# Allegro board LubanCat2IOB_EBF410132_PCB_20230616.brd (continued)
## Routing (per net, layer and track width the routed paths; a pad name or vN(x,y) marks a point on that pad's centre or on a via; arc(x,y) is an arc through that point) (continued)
VCC3V3_SD: length 133.2
  TOP w0.254: J1.15 35.78,21.16 36.04,20.9 36.28,21.14 J1.17
  TOP w0.381: v1(135.98,23.52) 133.25,23.52 132.66,22.93 v1(132.66,11.91) ; v1(37.05,11.26) 35.96,11.26 35.36,11.86 35.36,19.78 36.04,20.47 36.04,20.9
  ART03 w0.381: v1(37.05,11.26) 37.06,11.25 127.48,11.25 128.14,11.91 v1(132.66,11.91)
  BOTTOM w0.381: v1(135.98,23.52) C28.1 136.66,23.65 137.21,24.2 139.6,24.2 140.2,23.6 C30.1 J41.4
VCC5V0_SYS: length 183.1
  TOP w0.305: v1(135.52,97.61) 132.56,97.61 131.55,96.59 105.77,96.59 105.26,96.08 105.26,95.14 104.65,94.53 99.54,94.53 98.98,95.09 98.98,97.81 98.22,98.57 32.05,98.57 30.28,96.8 26.64,96.8 25.35,98.09 21.23,98.09 18.97,95.83 15.82,95.83 14.71,94.71 14.71,80.29 16.1,78.89 16.1,74.09 15.39,73.38 12.93,73.38 12.22,72.67 12.22,61.08 ; 10.19,60.91 10.19,71.11 9.88,71.41 C24.2 R11.2
  BOTTOM w0.305: R4.1 v1(135.52,97.61)
VCC5V0_USB: length 12.3
  TOP w0.305: R235.2 C140.2 5.44,72.72 v1(7.57,72.72)
  BOTTOM w0.305: C141.1 13.55,77.01 v1(14.04,77.49) ; v1(7.57,72.72) 11.02,72.72 11.55,73.24 C159.1
  vias: v1(14.04,76.49) v1(15.04,77.49) v1(15.04,76.49) v1(31.11,86.66) v1(31.11,85.66) v1(32.11,86.66) v1(32.11,85.66) v1(117.02,82.54) v1(118.02,82.54) v1(119.02,82.54) v1(121.59,97.48) v1(122.59,98.48) v1(122.59,97.48) v1(128.82,97.48) v1(129.82,98.48) v1(129.82,97.48)
VCC5V0_USB20_HOST2: length 16.3
  BOTTOM w0.508: C144.1 126,96.46 ; 126,96.46 126.62,97.08 126.62,98.03 126.11,98.54 C145.1 125.81,98.44 U24.1 ; 126,96.46 126.11,96.46 126.62,95.95 126.62,92.33 127.05,91.89 128.19,91.89 128.7,91.39 128.7,90.14 129.31,89.53 129.31,87.71 J19.10
VCC5V0_USB20_HUB: length 45.8
  TOP w0.305: J20.7 111.1,93.06 110.49,93.67 99.01,93.67 98.11,94.57 v1(97.21,94.57)
  TOP w0.508: U29.1 112.87,81.31 C161.1 C162.1 C165.1 C164.1 109.75,84.15 J20.1 J20.7
  BOTTOM w0.305: U28.19 105.37,97.24 104.06,98.56 C154.1 104,98.59 103.43,99.16 102.05,99.16 101.46,98.58 C155.1 101.46,97.81 101.13,97.48 97.64,97.48 97.21,97.05 v1(97.21,94.57)
VCC5V0_USB30_HOST: length 14.3
  BOTTOM w0.508: J19.1 129.85,93.24 131.34,94.74 134.16,94.74 134.52,95.09 134.52,97.41 133.93,97.99 C148.1 C149.1 132.26,98.44 U26.1
VCC_1V8: length 245.6
  TOP w0.254: J1.13 35.28,21.28 35.03,21.03 34.78,21.27 J1.11
  TOP w0.305: v1(17.36,34.58) 20.38,34.58 v1(20.43,34.63) 20.43,19.6 21.04,19 34.04,19
  TOP w0.381: v1(62.18,67.75) 62.2,67.74 L10.2 ; v1(63.75,16.68) C23.1 C22.1 v1(61.97,18.83) 61.97,16.6 61.52,16.15 61.52,8 60.78,7.26 35.33,7.26 34.75,7.84 34.75,18.28 34.04,19 34.65,19.6 34.65,20.14 35.03,20.52 35.03,21.03 ; L14.2 v1(81.43,67.74)
  ART04 w0.381: v1(61.97,18.83) 62.21,19.07 78.26,19.07 78.74,19.55 78.74,24.99 77.14,26.59 77.14,58.67 79.22,60.75 79.22,63.14 81.43,65.34 v1(81.43,67.74)
  BOTTOM w0.381: Q1.1 16.9,33.35 R45.1 v1(17.36,34.58) ; v1(62.18,67.75) 56,67.75 53.64,65.4 53.64,62.28 55.42,60.5 55.42,43.25 56.16,42.52 65.38,42.52 66.14,41.75 66.14,26.03 65.74,25.62 59.44,25.62 59.01,25.2 59.01,23.41 59.28,23.14 60.86,23.14 61.07,22.92 61.08,22.92 ; 61.08,22.92 R24.1 61.08,19.71 v1(61.97,18.83) ; 61.08,22.92 61.32,23.16 62.91,23.16 63.24,22.83 R25.1 ; U6.8 v1(63.75,16.68) ; v1(20.43,34.63) R46.1 19.98,33.4 Q2.1
VCCA_1V8: length 45
  TOP w0.254: J1.14 35.28,27.64 v1(35.04,27.89) 34.78,27.64 J1.12
  TOP w0.305: v1(64.28,30.89) 64.83,30.34 R219.1
  BOTTOM w0.381: v1(35.04,27.89) 35.68,27.25 52.04,27.25 52.5,26.79 54.79,26.79 55.32,27.33 55.32,29.21 54.94,29.59 53.98,29.59 53.41,30.16 53.41,32.57 53.98,33.14 63.5,33.14 64.28,32.36 v1(64.28,30.89)
VCCIO_ACODEC: length 73.1
  TOP w0.254: J1.19 36.78,23.64 v1(37.04,23.89) 37.28,23.64 J1.21
  TOP w0.381: v1(38.74,77.85) 38.74,76.53 38.36,76.15 v1(32.97,76.15)
  ART04 w0.381: v1(37.04,23.89) 37.04,46.63 36.27,47.39 34.04,47.39 33.27,48.15 33.27,62.51 31.65,64.13 31.65,74.82 v1(32.97,76.15)
  BOTTOM w0.381: R210.1 v1(38.74,77.85) R213.1
VDD_3V3: length 89.3
  TOP w0.305: R147.1 R146.1 61.32,70.44 v1(62.17,71.29) ; R6.2 C14.2 9.74,43.47 10.13,43.07 10.13,33.4 10.16,33.37 ; U12.5 3.07,23.16 3.29,22.94 4.31,22.94 4.57,23.2 v1(4.57,23.79) C21.1 ; U35.5 v1(144.08,64.88) ; C17.1 v1(8.76,23.79) 8.76,23.45 8.48,23.16 7.48,23.16 7.26,23.38 U4.5 ; U40.5 143.15,42.19 143.43,41.91 v1(144.71,41.91) ; L16.2 v1(82.21,80.43) ; L12.2 v1(63.11,80.25) ; v1(60.32,18.83) R33.1 R35.1
  TOP w0.381: L15.2 81.58,70.4 v1(81.31,70.13) ; v1(37.06,17.68) 36.54,18.2 L6.1 ; L7.2 66.38,16.6 65.81,16.02 63.41,16.02 v1(62.75,16.68) ; L11.2 63.06,70.4 v1(62.17,71.29) ; v1(47.57,17.68) 47.08,18.18 L5.1
  PWR05 w0.508: 12,14.97 J37.5 ; J37.5 12.73,15.7 ; J37.5 11.27,15.7 ; J37.5 12,16.43
  BOTTOM w0.305: R178.1 55.97,71.19 Q6.1 ; v1(9.76,85.21) 10.14,84.84 R72.1 ; R66.2 v1(150.5,95.86) ; v1(19.08,84.25) v1(19.08,83.25) 19.82,82.51 D21.2 ; v1(7.55,78.8) 7.55,77.7 7.23,77.38 R236.2 ; R180.1 52.88,70.74 53.19,71.04 53.19,72.31 53.49,72.61 55.14,72.61 Q6.1 ; v1(1.53,52.51) 4.21,52.51 4.44,52.74 R2.2 ; Q8.1 59.27,71.19 R181.1 ; Q8.1 58.5,72.56 56.74,72.56 Q6.1 ; Q8.1 59.84,72.36 61.87,72.36 62.17,72.06 v1(62.17,71.29) ; R48.1 v1(22.12,28.72) ; R31.1 v1(140.22,97.35) ; R47.1 v1(16.66,28.72) ; R32.1 v1(146.81,95.83)
  BOTTOM w0.381: U9.5 32.04,20.6 C37.1 v1(33.22,20.25) ; v1(20.82,18.09) 21.34,18.62 C40.1 21.34,19.11 U10.5
  vias: v1(9.17,32.46) v1(9.17,31.46) v1(10.17,32.46) v1(10.17,31.46) v1(11.17,32.46) v1(11.17,31.46) v1(96.42,22.94) v1(96.42,22.14) v1(142.66,13.29) v1(142.66,12.29) v1(143.08,65.88) v1(143.66,13.29) v1(143.66,12.29) v1(144.08,65.88) v1(145.71,41.91)
VDD_3V3_EDP_LCD: length 32.5
  TOP w0.305: J29.12 152.81,22.05 153.03,22.27 152.76,22.55 J29.13 ; R187.1 v1(149.22,20.75)
  TOP w0.508: 153.03,22.27 v1(153.39,22.27) 155.57,22.27 156.08,21.76 156.08,13.69 155.45,13.05 149.1,13.05 148.59,13.56 C184.1 C183.1 147.5,14.21 U37.1
  BOTTOM w0.305: v1(149.22,20.75) 153.09,20.75 153.39,21.05 v1(153.39,22.27)
VDD_3V3_EDP_TP: length 17.4
  BOTTOM w0.508: v1(104.16,20.62) v1(105.16,20.62) 105.92,20.62 108.1,22.81 112.17,22.81 112.73,22.25 112.73,14.84 J28.1
VDD_5V: length 65.8
  TOP w0.305: v1(144.08,68.72) 143.98,68.82 U36.5 ; U33.5 v1(144.08,57.52) ; C4.1 9.4,46.78 v1(9.17,46.55) ; 10.19,47.24 10.16,47.27 10.16,56.92 9.63,57.44 C2.2 R1.2 ; U39.5 143.15,37.8 v1(143.71,37.24) v1(144.71,37.24) v1(144.71,38.24) ; U34.5 v1(144.08,60.82)
  TOP w0.508: J37.3 16,16.43 ; J37.3 16,14.97 ; J37.3 16.73,15.7 ; J37.3 15.27,15.7
  ART04 w0.305: v1(47.26,90.8) v1(48.26,90.8)
  BOTTOM w0.305: Q7.1 51.46,72.74 49.43,72.74 48.95,73.22 48.95,90.7
  BOTTOM w0.381: 19.68,24.17 20.07,24.56 U10.3 ; 19.68,24.17 20.12,23.73 20.12,22.98 20.5,22.6 23.09,22.6 23.5,22.2 C38.1 23.99,19.09 24.23,19.33 U9.3 ; 19.68,24.17 C41.1 16.13,24.66 v1(15.9,24.89)
  vias: v1(9.17,45.55) v1(10.17,46.55) v1(10.17,45.55) v1(11.17,46.55) v1(11.17,45.55) v1(28.32,80.67) v1(29.32,80.67) v1(133.2,59.59) v1(133.2,58.59) v1(134.2,59.59) v1(134.2,58.59) v1(135.18,59.59) v1(135.2,58.59) v1(143.08,69.72) v1(143.08,61.72) v1(143.08,58.59) v1(144.08,69.72) v1(144.08,61.72) v1(144.08,58.59)
VDD_CAM0_5V: length 10.9
  TOP w0.305: C171.1 149.23,57.59 v1(149.28,57.54) v1(150.28,57.54)
  TOP w0.508: C171.1 C170.1 147.5,57.52 U33.1
  BOTTOM w0.305: J22.3 149.36,52.28 ; J22.1 149.36,51.28 ; J22.2 149.36,51.78
VDD_CAM1_5V: length 3
  TOP w0.508: U36.1 147.38,68.82 C174.1 C175.1
  vias: v1(149.28,69.01) v1(150.28,69.01)
VDD_LCD0_3V3: length 12.2
  TOP w0.305: J23.4 150.61,65.93 150.34,66.19 150.58,66.43 J23.5
  TOP w0.508: 150.34,66.19 149.71,66.19 149.49,65.97 v1(149.27,65.97) C190.1 C185.1 147.58,65.96 C191.1 147.52,64.88 U35.1
  BOTTOM w0.305: v1(149.27,65.97) 147.76,65.97 147.46,66.27 R222.1 R167.1
VDD_LCD0_5V: length 8.5
  TOP w0.508: 151.51,63.8 151.51,62.51 150.9,61.9 C186.1 C188.1 147.58,61.9 C187.1 147.52,60.82 U34.1
VDD_LCD1_3V3: length 10.8
  TOP w0.305: R224.1 v1(146.71,47.24) ; U40.1 147.52,43.04 C198.1 147.57,43.11 C196.1 C199.1 ; R223.1 v1(146.71,46.15)
  BOTTOM w0.305: v1(146.71,47.24) v1(146.71,46.15) 147.37,45.49 147.37,44.52 147.68,44.22 v1(149.35,44.22)
VDD_LCD1_5V: length 6.5
  TOP w0.508: 151.08,40.06 C194.1 C197.1 147.58,40.05 C195.1 147.52,38.97 U39.1
BAT_RTC: length 11
  BOTTOM w0.305: J16.1 17.92,77.47 18.22,77.77 22.38,77.77 22.64,78.03 D24.2 21.96,80.71 C67.1 22.42,81.81 D21.1
CAM0_NRST: length 125.8
  TOP w0.203: J2.76 75.78,27.89 75.78,30.34 76.1,30.65 121.41,30.65 123.6,28.47 132.74,28.47 v1(133.4,29.13)
  ART03 w0.142: v1(146.69,60.12) 146.69,57.68 146.35,57.35 144.77,57.35 v1(144.08,56.66)
  BOTTOM w0.203: v1(133.4,29.13) 133.4,31.41 133.71,31.72 150.82,31.72 151.26,32.16 151.26,48.23 150.85,48.64 144.45,48.64 144.08,49 v1(144.08,56.66) ; J22.22 147.59,61.78 146.69,60.88 v1(146.69,60.12)
CAM0_PWDN: length 183.8
  TOP w0.156: v1(43.05,10.26) 43.99,11.2 43.99,18.82 41.78,21.03 J1.39
  ART03 w0.142: v1(129.18,10.5) 129.18,9.96 128.89,9.67 101.27,9.67 99.35,7.75 82.41,7.75 80.87,9.29 44.02,9.29 v1(43.05,10.26)
  BOTTOM w0.156: J22.15 149.17,58.28 148.82,57.93 145.64,57.93 145.29,57.58 145.29,50.52 145.69,50.11 151.6,50.11 151.94,49.77 151.94,23.4 151.6,23.06 148.85,23.06 148.44,22.64 148.44,13.1 148.12,12.79 129.5,12.79 129.18,12.47 v1(129.18,10.5)
CAM0_PWR_EN: length 118.7
  TOP w0.156: v1(122.42,48.74) 121.89,49.27 111.15,49.27 110.83,49.59 110.83,54.47 110.52,54.78 97.23,54.78 94.51,52.07 46.1,52.07 45.78,52.38 J3.56 ; R174.1 v1(140.6,58.59)
  BOTTOM w0.156: v1(122.42,48.74) 122.51,48.74 123.22,49.45 123.22,52.64 123.53,52.96 140.44,52.96 140.6,53.11 v1(140.6,58.59)
CAM1_NRST: length 141.2
  TOP w0.203: J2.80 76.78,27.89 76.78,29.53 77.1,29.84 121,29.84 123.24,27.61 133.88,27.61 v1(135.4,29.13)
  ART04 w0.203: v1(153,79.61) 153,80.27 153.19,80.46 156.13,80.46 156.54,80.06 156.54,30.84 156.26,30.55 135.92,30.55 135.4,30.04 v1(135.4,29.13)
  BOTTOM w0.203: v1(153,79.61) 152.63,79.98 J24.22
CAM1_PWDN: length 143
  TOP w0.156: J2.78 76.28,29.88 76.6,30.2 121.22,30.2 123.41,28.01 133.28,28.01 v1(134.4,29.13)
  ART04 w0.142: v1(134.4,29.13) 134.4,30.54 135,31.14 155.82,31.14 156.11,31.42 156.11,71.11 155.82,71.4 154.62,71.4 154.33,71.68 154.33,79.28 v1(154,79.61)
  BOTTOM w0.156: v1(154,79.61) 154.33,79.28 154.33,76.35 153.9,75.92 153.01,75.92 152.45,76.48 J24.15
CAM1_PWR_EN: length 125.9
  TOP w0.156: v1(122.4,49.74) 111.62,49.74 111.3,50.05 111.3,54.95 110.99,55.27 97.02,55.27 94.32,52.57 46.6,52.57 46.28,52.89 J3.58 ; R185.1 139.98,68.26 139.98,63.93 v1(139.6,63.55)
  BOTTOM w0.156: v1(122.4,49.74) 122.76,50.1 122.76,53.15 123.07,53.46 139.6,53.46 140.11,53.97 140.11,63.04 v1(139.6,63.55)
CAN1_H: length 20.6
  BOTTOM w0.254: U9.7 31.42,18.06 31.79,18.43 32.15,18.43 R39.1 32.63,18.44 32.99,18.44 33.3,18.13 33.3,15.77 33.05,15.52 31.95,15.52 31.42,14.98 31.42,10.99 31.95,10.46 35.06,10.46 35.56,10.96 35.56,13.28 35.84,13.56 J5.1
CAN1_L: length 20.2
  BOTTOM w0.254: J5.2 34.83,13.56 35.15,13.23 35.15,11.13 34.9,10.87 32.12,10.87 31.85,11.14 31.85,14.83 32.13,15.11 33.44,15.11 33.71,15.38 33.71,18.3 33.11,18.89 32.68,18.89 R39.2 32.1,18.9 31.64,18.9 31.22,19.33 U9.6
CAN1_RX_M1: length 79.8
  TOP w0.156: J4.9 v1(59.28,64.94)
  ART04 w0.142: v1(56,31.48) 56,32.68 56.77,33.45 56.77,59.94 59.28,62.46 v1(59.28,64.94)
  BOTTOM w0.156: U9.4 27.23,20.6 29.92,23.29 29.92,25.55 30.48,26.11 51.31,26.11 51.66,25.75 56.21,25.75 57.83,27.37 57.83,31.65 57.52,31.96 56.49,31.96 v1(56,31.48)
CAN1_TX_M1: length 90.6
  TOP w0.156: v1(58.28,65.94) 58.78,65.44 J4.7
  ART04 w0.142: v1(58.28,65.94) 58.76,65.46 58.76,62.63 56.38,60.25 56.38,33.77 55.52,32.91 55.52,30.96 v1(56,30.48)
  BOTTOM w0.156: v1(56,30.48) 55.52,30.96 55.52,31.84 56.03,32.36 57.88,32.36 58.19,32.04 58.19,27.1 56.54,25.45 51.41,25.45 51.08,25.78 30.78,25.78 30.25,25.24 30.25,23.11 29.01,21.87 29.01,19.11 28.69,18.79 27.34,18.79 27.01,18.46 27.01,17.14 26.65,16.79 U9.1
CAN2_H: length 21.9
  BOTTOM w0.254: 29.59,13.56 28.24,13.56 27.91,13.23 27.91,11.59 27.24,10.92 24.06,10.92 23.83,11.16 23.42,11.56 23.42,16.23 22.78,16.86 19.8,16.86 19.25,17.4 19.25,18.77 R42.1 19.23,19.39 19.23,19.76 18.8,20.19 U10.7
CAN2_L: length 20.5
  BOTTOM w0.254: U10.6 20.07,20.19 19.63,19.76 19.63,19.39 R42.2 19.66,18.83 19.66,17.57 19.96,17.27 22.95,17.27 23.83,16.4 23.83,11.73 24.23,11.32 27.08,11.32 27.51,11.76 27.51,13.15 27.1,13.56 J5.4
CAN2_RX: length 4.7
  BOTTOM w0.254: U10.4 21.34,27.82 R48.2 20.93,29.22 Q2.3
CAN2_RX_M0: length 81.1
  TOP w0.156: J4.8 v1(58.78,57.94)
  ART04 w0.142: v1(57,31.48) 57,32.26 58.31,33.56 58.31,57.46 v1(58.78,57.94)
  BOTTOM w0.156: Q2.2 21.43,32.85 R46.2 21.43,34.99 21.87,35.43 31.67,35.43 32.08,35.02 32.08,26.75 32.39,26.44 32.96,26.44 32.97,26.43 51.52,26.43 51.89,26.06 55.89,26.06 56.57,26.74 56.57,29.33 57.51,30.27 57.51,30.97 v1(57,31.48)
CAN2_TX: length 4.6
  BOTTOM w0.254: U10.1 17.53,27.89 R47.2 17.86,29.22 Q1.3
CAN2_TX_M0: length 84.5
  TOP w0.156: J4.10 59.28,57.44 v1(58.78,56.94)
  ART04 w0.142: v1(57,30.48) 57.63,31.11 57.63,32.08 58.78,33.23 v1(58.78,56.94)
  BOTTOM w0.156: Q1.2 18.81,33.35 R45.2 18.36,35.73 18.67,36.04 32.4,36.04 32.72,35.73 32.72,27.12 33.1,26.74 51.74,26.74 52.11,26.37 55.61,26.37 56.16,26.92 56.16,29.63 v1(57,30.48)
CC1: length 5.1
  TOP w0.156: v1(24.45,97.09) 24.45,97.04 25.05,96.43 J36.A5
  BOTTOM w0.156: D27.2 v1(24.45,97.09)
CC2: length 5.1
  TOP w0.156: v1(22.54,97.09) 22.54,97.04 22.05,96.54 J36.B5
  BOTTOM w0.156: D27.1 v1(22.54,97.09)
CTP0_INT: length 166.8
  TOP w0.156: J3.8 33.78,50.94 34.1,50.63 95.2,50.63 97.75,53.18 109.29,53.18 109.6,52.87 109.6,48.16 109.91,47.85 121.94,47.85 v1(122.42,47.36) ; J23.11 v1(153.96,69.43)
  ART03 w0.142: v1(153.96,69.43) 154.46,69.92 155.24,69.92 155.47,69.69 155.47,68.63 155.12,68.27 153.54,68.27 153.26,67.99 153.26,62.73 152.86,62.33 137.97,62.33 137.67,62.02 137.67,58.77 135.99,57.1 123.42,57.1 123.01,56.68 123.01,47.95 v1(122.42,47.36)
  BOTTOM w0.156: v1(153.96,69.43) 152.94,69.43 152.02,68.5 148.71,68.5 R167.2
CTP0_RST: length 167.5
  TOP w0.156: v1(121.42,47.36) 109.48,47.36 109.17,47.67 109.17,52.36 108.86,52.68 97.95,52.68 95.41,50.13 33.6,50.13 33.28,50.44 J3.6 ; J23.12 154.18,69.93 154.68,69.43 v1(154.96,69.43)
  ART03 w0.142: v1(154.96,69.43) 154.34,68.8 152.45,68.8 152.2,68.55 152.2,63.67 151.87,63.34 145.24,63.34 144.88,62.99 137.57,62.99 137.13,62.56 137.13,58.9 136.32,58.09 122.84,58.09 122.56,57.8 122.56,51.28 121.9,50.63 121.9,47.84 v1(121.42,47.36)
  BOTTOM w0.156: R222.2 148.74,67.52 151.54,67.52 152.96,68.93 154.47,68.93 v1(154.96,69.43)
CTP1_INT: length 114
  TOP w0.156: J26.11 149.13,46.69 R223.2 148.02,46.71 146.3,46.71 145.75,47.27 139.84,47.27 139.52,46.95 139.52,44.26 139.21,43.95 124.6,43.95 124.28,44.26 124.28,50.66 123.87,51.08 112.87,51.08 112.56,51.39 112.56,58.13 112.24,58.44 94.78,58.44 v1(94.09,57.75) ; J4.49 v1(69.28,64.94)
  ART03 w0.142: v1(69.28,64.94) 69.28,54.76 69.57,54.48 91.11,54.48 91.29,54.66 91.29,56.47 91.57,56.75 93.09,56.75 v1(94.09,57.75)
CTP1_RST: length 112.3
  TOP w0.156: J26.12 148.63,47.19 R224.2 148,47.82 139.4,47.82 139.09,47.51 139.09,44.69 138.78,44.37 124.98,44.37 124.66,44.69 124.66,51.19 124.35,51.51 113.3,51.51 112.99,51.82 112.99,58.54 112.68,58.85 94.18,58.85 v1(93.09,57.75) ; J4.53 v1(70.28,64.94)
  ART03 w0.142: v1(70.28,64.94) 70.28,55.22 70.57,54.94 90.65,54.94 90.83,55.11 90.83,56.89 91.12,57.17 92.51,57.17 v1(93.09,57.75)
DGB_RX: length 6.8
  BOTTOM w0.156: J7.2 5.25,16.26 5.82,16.83 D36.1 5.82,18.93 R36.1
DGB_TX: length 6.9
  BOTTOM w0.156: R23.1 5.82,21.6 D37.1 2.88,20.96 2.32,20.4 J7.1
DSI0_RST: length 152.8
  TOP w0.156: J23.15 150.37,71.43 v1(150.29,71.34) ; v1(121.42,48.74) 110.73,48.74 110.39,49.08 110.39,53.96 110.08,54.28 97.34,54.28 94.65,51.58 36.1,51.58 35.78,51.9 J3.16
  ART03 w0.142: v1(121.42,48.74) 121.42,50.78 122.17,51.53 122.17,58.82 122.46,59.1 136.27,59.1 136.65,59.48 136.65,63.95 137.06,64.36 150.93,64.36 151.23,64.66 151.23,71.14 151.03,71.34 v1(150.29,71.34)
DSI0_TE: length 164.5
  TOP w0.156: J3.4 32.78,50.02 33.1,49.7 95.69,49.7 98.15,52.17 108.42,52.17 108.74,51.85 108.74,47.16 109.05,46.85 121.94,46.85 v1(122.42,46.36) ; v1(142.63,76.65) 142.63,76.09 143.66,75.05 143.66,71.94 144.01,71.6 146.08,71.6 146.53,72.06 R204.1
  BOTTOM w0.156: v1(122.42,46.36) 121.91,46.87 121.91,50.29 122.3,50.68 122.3,64.05 122.81,64.56 125.57,64.56 125.73,64.72 125.73,67.74 125.98,67.99 133.93,67.99 134.57,68.63 134.57,76.02 135.25,76.7 142.58,76.7 v1(142.63,76.65)
DSI1_RST: length 150.4
  TOP w0.156: J4.57 v1(71.28,64.94) ; v1(146.71,37.24) 147.46,37.99 155.6,37.99 155.98,38.38 155.98,46.68 153.97,48.69 J26.15
  ART03 w0.142: v1(71.28,64.94) 71.28,63.13 71.78,62.63 74.07,62.63 74.3,62.4 74.3,61.69 74.8,61.18 74.8,57.2 75.09,56.92 87.76,56.92 88.04,57.2 88.04,59.99 88.32,60.27 93.57,60.27 v1(94.09,59.75) ; v1(93.8,28.85) 94.28,28.37 130.76,28.37 132.36,29.97 132.36,34.26 133.78,35.68 141.42,35.68 141.71,35.97 141.71,37.48 141.99,37.76 146.19,37.76 v1(146.71,37.24)
  BOTTOM w0.156: v1(94.09,59.75) 94.09,59.45 94.92,58.62 94.92,30.4 93.8,29.28 v1(93.8,28.85)
DSI1_TE: length 104.2
  TOP w0.156: J4.55 v1(70.78,61.94) ; v1(92.09,57.75) 93.58,59.25 113.06,59.25 113.37,58.94 113.37,52.2 113.68,51.89 124.71,51.89 125.02,51.58 125.02,45.09 125.33,44.78 138.37,44.78 138.68,45.09 138.68,48.04 139,48.36 R208.1
  ART03 w0.142: v1(70.78,61.94) 71.3,61.42 71.3,55.58 71.58,55.29 90.09,55.29 90.37,55.58 90.37,57.47 90.66,57.75 v1(92.09,57.75)
EDP_AUXN: length 5.5
  TOP w0.124: C178.2 R188.2 148.11,21.61 149.58,21.61 150.23,20.96 150.55,20.96 150.64,21.05 J29.10
EDP_AUXP: length 5.5
  TOP w0.124: J29.9 150.64,20.55 150.55,20.63 150.1,20.63 149.44,21.29 148.12,21.29 R187.2 C177.2
EDP_BL_EN: length 132.6
  TOP w0.156: J29.22 v1(150.39,27.05) ; v1(150.39,28.05) 149.77,28.05 149.53,27.81 149.53,25.54 149.2,25.22 143.42,25.22 143.1,25.54 143.1,35.68 142.72,36.06 137.63,36.06 137.31,36.38 137.31,42.79 137,43.1 123.88,43.1 123.56,43.41 123.56,49.95 123.25,50.26 112.06,50.26 111.74,50.58 111.74,57.37 111.43,57.68 95.73,57.68 94.31,56.26 v1(92.09,56.26) ; J4.45 v1(68.28,64.94)
  ART03 w0.142: v1(92.09,56.26) 92.09,54.28 91.8,53.99 68.57,53.99 68.28,54.28 v1(68.28,64.94)
  BOTTOM w0.156: v1(150.39,28.05) v1(150.39,27.05)
EDP_BL_PWM: length 155
  TOP w0.156: J3.14 35.28,51.41 35.6,51.1 94.89,51.1 97.54,53.74 109.66,53.74 109.97,53.43 109.97,48.53 110.28,48.22 122.83,48.22 123.14,47.91 123.14,43.01 123.45,42.69 136.54,42.69 136.86,42.38 136.86,35.97 137.17,35.66 142.41,35.66 142.72,35.34 142.72,25.23 143.04,24.91 149.38,24.91 149.83,25.37 149.83,27.2 150.18,27.55 J29.23
EDP_HPDIN_M0: length 88.8
  TOP w0.156: J2.66 73.28,30.48 74.4,31.6 129.54,31.6 130.48,30.65 140.43,30.65 140.74,30.34 140.74,24.86 141.05,24.55 J29.17
EDP_LCD_PWR_EN: length 148.3
  TOP w0.156: v1(107.31,55.8) 96.84,55.8 94.15,53.11 47.1,53.11 46.78,53.42 J3.60 ; R189.2 139.59,14.27 139.28,14.58 139.28,29.35 138.94,29.69 132.94,29.69 v1(132.38,29.13)
  ART03 w0.142: v1(132.38,29.13) 132.38,28.32 132.1,28.04 121.64,28.04 121.01,27.4 v1(108.31,27.4)
  BOTTOM w0.156: v1(107.31,55.8) 108.86,54.25 108.86,37.11 108.55,36.8 107.29,36.8 106.98,36.5 106.98,27.68 107.26,27.4 v1(108.31,27.4)
EDP_TP_INT: length 109.4
  TOP w0.156: v1(78.78,27.89) 78.78,28.69 79.1,29 91.98,29 94.16,26.82 94.16,18.75 94.47,18.44 107.49,18.44 108.09,19.03 108.09,20.14 v1(107.61,20.62) R193.2 ; J4.51 v1(69.78,61.94)
  BOTTOM w0.156: v1(78.78,27.89) 78.52,27.89 78,27.38 77.52,27.38 77.27,27.63 77.27,50.62 76.83,51.05 62.74,51.05 62.05,51.74 62.05,58.29 63.02,59.25 65.42,59.25 68.58,62.42 69.3,62.42 v1(69.78,61.94) ; v1(107.61,20.62) 110.64,20.62 110.95,20.31 J28.2
EDP_TP_PWR_EN: length 106
  TOP w0.156: J3.64 47.78,54.33 48.1,54.02 93.7,54.02 96.48,56.8 v1(107.31,56.8) ; R191.1 v1(100.05,26.51)
  BOTTOM w0.156: v1(100.05,26.51) 100.05,36.95 100.36,37.26 108.22,37.26 108.53,37.57 108.53,53.77 106.78,55.52 106.78,56.27 v1(107.31,56.8)
EDP_TP_RESET: length 100.7
  TOP w0.203: J4.47 v1(68.78,61.94) ; v1(77.78,27.89) 77.78,29.12 78.1,29.43 92.08,29.43 94.54,26.97 94.54,19.31 94.85,19 106.32,19 R194.2 v1(107.61,19.6)
  BOTTOM w0.203: J28.3 108.95,19.24 108.59,19.6 v1(107.61,19.6) ; v1(68.78,61.94) 65.69,58.85 63.3,58.85 62.46,58.01 62.46,52.17 63.14,51.48 77.44,51.48 77.8,51.13 77.8,27.91 v1(77.78,27.89)
EDP_TX_AUXN: length 99.5
  TOP w0.124: J2.62 72.28,27.63 72.2,27.72 72.2,31.33 73.22,32.35 130.46,32.35 131.32,31.49 138,31.49 139.78,33.27 140.16,33.27 v1(140.46,32.97) ; C178.1 v1(145.55,22.79)
  ART03 w0.113: v1(140.46,32.97) 140.77,33.28 141.28,33.28 arc(141.37,33.24) 141.4,33.16 arc(141.44,33.08) 141.52,33.04 141.73,33.04 arc(141.82,33.08) 141.85,33.16 arc(141.89,33.24) 141.97,33.28 142.54,33.28 142.74,33.08 142.74,31.59 143.05,31.27 143.67,31.27 143.8,31.14 143.8,30.95 143.67,30.82 143.05,30.82 142.74,30.5 142.74,30.05 143.05,29.73 143.67,29.73 143.8,29.6 143.8,29.41 143.67,29.28 143.05,29.28 142.74,28.97 142.74,28.15 arc(142.71,28.08) 142.64,28.05 arc(142.57,28.02) 142.54,27.95 142.54,27.69 arc(142.57,27.63) 142.64,27.6 arc(142.71,27.57) 142.74,27.5 142.74,27.24 arc(142.71,27.18) 142.64,27.15 arc(142.57,27.12) 142.54,27.05 142.54,26.79 arc(142.57,26.72) 142.64,26.7 arc(142.71,26.67) 142.74,26.6 142.74,24.66 143.13,24.27 144.12,24.27 arc(144.21,24.23) 144.25,24.13 arc(144.29,24.04) 144.38,24 144.57,24 arc(144.66,24.04) 144.7,24.13 arc(144.74,24.23) 144.84,24.27 145.02,24.27 arc(145.11,24.23) 145.15,24.13 arc(145.19,24.04) 145.29,24 145.47,24 arc(145.56,24.04) 145.6,24.13 arc(145.64,24.23) 145.74,24.27 145.92,24.27 arc(146.02,24.23) 146.06,24.13 arc(146.09,24.04) 146.19,24 146.37,24 arc(146.47,24.04) 146.51,24.13 arc(146.55,24.23) 146.64,24.27 146.88,24.27 147.11,24.04 147.11,22.58 146.77,22.25 145.66,22.25 145.55,22.36 v1(145.55,22.79)
EDP_TX_AUXP: length 99.4
  TOP w0.124: v1(140.46,33.9) 140.16,33.6 139.65,33.6 137.87,31.82 131.45,31.82 130.6,32.67 73.08,32.67 71.87,31.46 71.87,27.72 71.78,27.63 J2.60 ; C177.1 v1(145.55,21.39)
  ART03 w0.113: v1(145.55,21.39) 145.55,21.82 145.66,21.93 146.9,21.93 147.42,22.45 147.42,24.17 147.01,24.58 143.26,24.58 143.05,24.79 143.05,28.83 143.18,28.97 143.8,28.97 144.12,29.28 144.12,29.73 143.8,30.05 143.18,30.05 143.05,30.18 143.05,30.37 143.18,30.5 143.8,30.5 144.12,30.82 144.12,31.27 143.8,31.58 143.18,31.58 143.05,31.72 143.05,33.21 142.67,33.59 140.77,33.59 v1(140.46,33.9)
EDP_TX_D0N: length 105
  TOP w0.124: J2.44 67.78,27.63 67.7,27.72 67.7,32.13 70.02,34.45 136.56,34.45 137.14,33.87 137.14,33.07 v1(136.84,32.77) ; J29.6 150.64,19.05 150.55,19.13 149.68,19.13 arc(149.6,19.1) 149.56,19.01 arc(149.53,18.93) 149.44,18.89 149.18,18.89 arc(149.1,18.93) 149.07,19.01 arc(149.03,19.1) 148.95,19.13 148.69,19.13 arc(148.6,19.1) 148.57,19.01 arc(148.53,18.93) 148.45,18.89 148.19,18.89 arc(148.11,18.93) 148.07,19.01 arc(148.04,19.1) 147.95,19.13 145.21,19.13 v1(144.91,18.83)
  ART03 w0.113: v1(144.91,18.83) 144.6,19.14 142.58,19.14 141.39,20.33 141.39,30.65 140.56,31.48 137.68,31.48 137.17,31.99 137.17,32.43 v1(136.84,32.77)
EDP_TX_D0P: length 105.3
  TOP w0.124: v1(137.76,32.77) 137.46,33.07 137.46,34.01 136.7,34.78 69.88,34.78 67.37,32.26 67.37,27.72 67.28,27.63 J2.42 ; v1(144.91,19.72) 145.16,19.46 150.55,19.46 150.64,19.55 J29.7
  ART03 w0.113: v1(144.91,19.72) 144.64,19.45 142.71,19.45 141.71,20.46 141.71,30.78 140.69,31.79 139.81,31.79 arc(139.75,31.82) 139.73,31.87 arc(139.71,31.93) 139.65,31.95 139.36,31.95 arc(139.3,31.93) 139.28,31.87 arc(139.26,31.82) 139.2,31.79 138.91,31.79 arc(138.85,31.82) 138.83,31.87 arc(138.81,31.93) 138.75,31.95 138.46,31.95 arc(138.4,31.93) 138.38,31.87 arc(138.36,31.82) 138.3,31.79 137.81,31.79 137.49,32.12 137.49,32.5 v1(137.76,32.77)
EDP_TX_D1N: length 106.3
  TOP w0.124: J29.3 150.64,17.55 150.55,17.63 149.82,17.63 arc(149.75,17.61) 149.73,17.54 arc(149.7,17.47) 149.63,17.45 149.32,17.45 arc(149.26,17.47) 149.23,17.54 arc(149.2,17.61) 149.14,17.63 148.83,17.63 arc(148.76,17.61) 148.73,17.54 arc(148.71,17.47) 148.64,17.45 148.33,17.45 arc(148.27,17.47) 148.24,17.54 arc(148.21,17.61) 148.14,17.63 146.76,17.63 v1(146.48,17.35) ; J2.48 68.78,27.63 68.7,27.72 68.7,31.46 70.77,33.53 132.05,33.53 132.58,32.99 134.62,32.99 v1(134.92,32.69)
  ART03 w0.113: v1(134.92,32.69) 135.23,33 135.44,33 135.55,32.88 135.55,31.51 135.42,31.38 134.76,31.38 134.44,31.06 134.44,30.61 134.76,30.3 140.07,30.3 140.48,29.89 140.48,18.3 141.12,17.65 146.18,17.65 v1(146.48,17.35)
EDP_TX_D1P: length 106.6
  TOP w0.124: v1(134.92,33.62) 134.62,33.32 132.72,33.32 132.18,33.85 70.63,33.85 68.37,31.59 68.37,27.72 68.28,27.63 J2.46 ; v1(146.48,18.24) 146.76,17.96 150.55,17.96 150.64,18.05 J29.4
  ART03 w0.113: v1(134.92,33.62) 135.23,33.31 135.57,33.31 135.86,33.01 135.86,31.38 135.55,31.06 134.89,31.06 134.76,30.93 134.76,30.74 134.89,30.61 136.31,30.61 arc(136.36,30.64) 136.39,30.7 arc(136.41,30.76) 136.47,30.78 136.76,30.78 arc(136.82,30.76) 136.84,30.7 arc(136.87,30.64) 136.92,30.61 140.2,30.61 140.79,30.02 140.79,18.43 141.25,17.97 146.21,17.97 v1(146.48,18.24)
EXT_PWR_EN: length 51.9
  TOP w0.156: J1.27 v1(38.78,23.89)
  TOP w0.254: U2.5 v1(1.81,39.54)
  ART03 w0.142: v1(18.06,38.12) 33.83,38.12 37.35,34.6 37.35,25.94 38.78,24.51 v1(38.78,23.89)
  BOTTOM w0.156: v1(18.06,38.12) 3.75,38.12 3.44,38.43 R8.1 v1(1.81,39.54)
FAN_CTRL: length 12.2
  TOP w0.156: J3.5 33.28,65.88 32.97,66.19 v1(28.96,66.19)
  BOTTOM w0.156: R10.1 v1(28.96,66.19)
FSPI_CLK: length 10.4
  TOP w0.156: v1(64.78,24.89) 64.28,24.39 J2.29
  BOTTOM w0.156: v1(64.78,24.89) 64.29,24.39 64.29,21.84 63.78,21.33 63.78,19.53 64.08,19.22 U6.6
FSPI_CS0N: length 12.3
  TOP w0.156: J2.31 64.78,20.86 64.44,20.52 61.42,20.52 61.11,20.21 61.11,17.19 60.6,16.68 v1(59.11,16.68)
  BOTTOM w0.156: U6.1 v1(59.11,16.68)
FSPI_D0: length 30.5
  TOP w0.156: J32.1 78.24,19.86 77.93,20.17 v1(77.93,21.94) ; v1(65.78,24.89) 65.28,24.39 J2.33
  ART04 w0.142: v1(77.93,21.94) 67.57,21.94 67.28,22.23 67.28,25.29 67.06,25.52 66.04,25.52 65.78,25.27 v1(65.78,24.89)
  BOTTOM w0.156: U6.5 64.54,20.49 64.34,20.7 64.34,21.18 64.72,21.56 64.72,23.83 v1(65.78,24.89)
FSPI_D1: length 14.5
  TOP w0.156: J2.35 v1(65.78,23.89)
  ART04 w0.142: v1(60.32,19.83) 61.18,19.83 61.42,20.06 61.42,21.49 61.56,21.64 65.5,21.64 65.79,21.92 65.79,23.89 v1(65.78,23.89)
  BOTTOM w0.156: v1(60.32,19.83) 59.46,18.97 59.46,18.33 59.08,17.95 U6.2
FSPI_D2: length 17.3
  TOP w0.156: v1(66.78,24.89) 66.28,24.39 J2.37
  ART04 w0.142: v1(66.78,24.89) 66.27,24.38 65.43,24.38 65.1,24.05 65.1,22.4 64.82,22.12 60.36,22.12 60.08,21.83 v1(60.08,21)
  BOTTOM w0.156: R24.2 v1(60.08,21) 60.08,20.32 58.98,19.22 U6.3
FSPI_D3: length 14.7
  TOP w0.156: J2.39 v1(66.78,23.89)
  ART04 w0.142: v1(66.78,23.89) 66.78,21.72 66.07,21 v1(62.97,21)
  BOTTOM w0.156: U6.7 63.42,17.95 62.97,18.41 v1(62.97,21) 62.24,21.73 R25.2
GMAC0_INT: length 59.9
  TOP w0.156: v1(77.73,66.47) 78.66,66.47 79.04,66.85 79.04,71.52 78.51,72.06 R104.1 ; J2.70 74.28,28.39 v1(74.78,28.89)
  ART04 w0.142: v1(77.73,66.47) 77.73,65.62 76.14,64.03 68.53,64.03 68.25,63.74 68.25,60.85 70.28,58.82 70.28,38.2 74.78,33.7 v1(74.78,28.89)
GMAC0_MCLKINOUT: length 67.6
  TOP w0.156: J2.77 76.28,24.08 76.61,24.41 77.3,24.41 v1(77.78,24.89) ; R105.1 v1(77.6,76.12)
  ART04 w0.142: v1(77.78,24.89) 76.23,26.45 76.23,34.21 71.29,39.15 71.29,62.63 71.57,62.91 76.61,62.91 79.71,66.01 79.71,75.71 79.3,76.12 v1(77.6,76.12)
  BOTTOM w0.156: v1(77.6,76.12) 77.44,76.28 R106.1
GMAC0_MDC: length 86.7
  TOP w0.156: v1(76.78,24.89) 76.48,24.89 76,24.41 75.44,24.41 75.28,24.25 J2.73 ; v1(65.59,76.64) 66.45,77.5 U18.13
  ART04 w0.142: v1(65.59,76.64) 66.13,77.19 67.82,77.19 68,77.36 68,78.48 68.63,79.12 75.74,79.12 76.17,78.69 76.17,74.14 76.71,73.61 78.94,73.61 79.27,73.28 79.27,66.14 76.4,63.27 70.59,63.27 70.31,62.98 70.31,60.35 70.94,59.71 70.94,38.86 75.77,34.03 75.77,25.91 v1(76.78,24.89)
  BOTTOM w0.156: R101.2 64.7,76.64 v1(65.59,76.64)
GMAC0_MDIO: length 83.9
  TOP w0.156: v1(66.59,76.64) 67.05,77.1 U18.14 ; v1(75.78,24.89) 75.11,24.89 74.78,24.56 J2.71
  ART04 w0.142: v1(66.59,76.64) 68.16,76.64 68.35,76.83 68.35,77.87 68.63,78.15 75.52,78.15 75.72,77.96 75.72,73.99 77.22,72.49 78.59,72.49 78.88,72.2 78.88,66.28 76.25,63.65 69.59,63.65 69.31,63.36 69.31,60.59 70.61,59.28 70.61,38.57 75.29,33.9 75.29,25.39 v1(75.78,24.89)
  BOTTOM w0.156: R102.2 65.87,77.36 v1(66.59,76.64)
GMAC0_RSTN: length 69
  TOP w0.156: J2.72 v1(74.78,27.89) ; v1(66.59,72.64) 66.44,72.79 D22.2
  ART04 w0.142: v1(66.59,72.64) 67.07,73.12 67.07,74.1 67.41,74.44 73.58,74.44 75.67,72.36 75.67,67.59 74.8,66.72 74.8,64.69 74.52,64.41 68.08,64.41 67.79,64.13 67.79,60.58 69.29,59.08 69.29,38.55 74.31,33.54 74.31,28.37 v1(74.78,27.89)
GMAC0_RXCLK: length 64.3
  TOP w0.156: R95.1 v1(73.05,69.06) R98.1 ; v1(70.78,24.89) 71.28,24.39 J2.57
  ART04 w0.142: v1(73.05,69.06) 73.05,69.16 71.42,70.79 63.28,70.79 62.99,70.5 62.99,67.26 62.79,67.05 62.79,40.26 69.82,33.22 69.82,26.21 70.78,25.25 v1(70.78,24.89)
GMAC0_RXD0: length 65.3
  TOP w0.156: v1(74.28,24.89) 73.78,24.39 J2.67 ; R91.1 v1(70.76,69.06) R88.2
  ART04 w0.142: v1(70.76,69.06) 70.76,67.8 70.48,67.51 67.19,67.51 66.8,67.13 66.8,58.92 67.28,58.44 67.28,52.85 67.12,52.68 66.81,52.68 66.64,52.51 66.64,52.28 66.81,52.11 67.12,52.11 67.28,51.94 67.28,51.71 67.12,51.54 66.81,51.54 66.64,51.37 66.64,51.14 66.81,50.97 67.12,50.97 67.28,50.8 67.28,50.57 67.12,50.4 66.81,50.4 66.64,50.23 66.64,50 66.81,49.83 67.12,49.83 67.28,49.67 67.28,49.43 67.12,49.26 66.81,49.26 66.64,49.1 66.64,48.86 66.81,48.69 67.12,48.69 67.28,48.53 67.28,48.29 67.12,48.12 66.81,48.12 66.64,47.96 66.64,47.72 66.81,47.55 67.12,47.55 67.28,47.39 67.28,47.15 67.12,46.98 66.81,46.98 66.64,46.82 66.64,46.58 66.81,46.41 67.12,46.41 67.28,46.25 67.28,45.98 67.12,45.81 66.59,45.81 66.42,45.64 66.42,45.41 66.59,45.24 67.12,45.24 67.28,45.07 67.28,44.84 67.12,44.67 66.59,44.67 66.42,44.5 66.42,44.27 66.59,44.1 67.12,44.1 67.28,43.93 67.28,43.7 67.12,43.53 66.59,43.53 66.42,43.36 66.42,43.13 66.59,42.96 67.24,42.96 67.41,42.79 67.41,42.56 67.24,42.39 66.94,42.39 66.8,42.25 66.8,39.67 73.28,33.19 73.28,26.82 74.28,25.81 v1(74.28,24.89)
GMAC0_RXD1: length 64.2
  TOP w0.156: v1(72.78,24.89) 73.28,24.39 J2.65 ; R92.1 v1(69.62,69.06) R89.2
  ART04 w0.142: v1(72.78,24.89) 72.78,25.69 71.86,26.62 71.86,33.35 64.14,41.07 64.14,46.32 64.48,46.66 65.5,46.66 65.79,46.94 65.79,47.35 65.62,47.51 65.38,47.51 65.21,47.68 65.21,47.92 65.38,48.08 65.62,48.08 65.79,48.25 65.79,48.49 65.62,48.65 65.38,48.65 65.21,48.82 65.21,49.06 65.38,49.22 65.62,49.22 65.79,49.39 65.79,49.63 65.62,49.79 65.38,49.79 65.21,49.96 65.21,50.2 65.38,50.36 65.62,50.36 65.79,50.53 65.79,50.77 65.62,50.93 65.38,50.93 65.21,51.1 65.21,51.34 65.38,51.5 65.62,51.5 65.79,51.67 65.79,51.91 65.62,52.07 65.38,52.07 65.21,52.24 65.21,52.48 65.38,52.64 65.62,52.64 65.79,52.81 65.79,53.05 65.62,53.21 65.38,53.21 65.21,53.38 65.21,53.62 65.38,53.78 65.62,53.78 65.79,53.95 65.79,54.19 65.62,54.35 65.38,54.35 65.21,54.52 65.21,54.76 65.38,54.92 65.62,54.92 65.79,55.09 65.79,55.33 65.62,55.49 65.38,55.49 65.21,55.66 65.21,55.9 65.38,56.06 65.62,56.06 65.79,56.23 65.79,62.33 65.33,62.78 65.33,68.25 65.53,68.45 67.56,68.45 67.87,68.75 67.87,69.36 68.13,69.62 69.06,69.62 v1(69.62,69.06)
GMAC0_RXD2: length 64
  TOP w0.156: R97.1 v1(68.48,69.06) R93.1 ; J2.63 v1(72.78,23.89)
  ART04 w0.142: v1(72.78,23.89) 73.28,24.39 73.28,25.8 72.28,26.79 72.28,33.55 66.21,39.62 66.21,40.66 66.05,40.83 65.06,40.83 64.9,41 64.9,41.23 65.06,41.4 65.67,41.4 65.83,41.57 65.83,41.8 65.67,41.97 65.06,41.97 64.9,42.14 64.9,42.37 65.06,42.54 65.67,42.54 65.83,42.71 65.83,42.98 65.67,43.14 64.75,43.14 64.59,43.31 64.59,43.55 64.75,43.71 65.67,43.71 65.83,43.88 65.83,44.12 65.67,44.28 64.75,44.28 64.59,44.45 64.59,44.69 64.75,44.85 65.67,44.85 65.83,45.02 65.83,45.26 65.67,45.42 64.75,45.42 64.59,45.59 64.59,45.83 64.75,45.99 66.05,45.99 66.21,46.16 66.21,62.64 65.79,63.06 65.79,67.61 66.14,67.97 68.25,67.97 68.5,68.22 68.5,69.03 v1(68.48,69.06)
GMAC0_RXD3: length 64
  TOP w0.156: R94.1 v1(67.34,69.06) R90.2 ; v1(71.78,24.89) 72.28,24.39 J2.61
  ART04 w0.142: v1(67.34,69.06) 66.85,69.54 65.07,69.54 64.79,69.26 64.79,53.25 64.62,53.08 63.84,53.08 63.67,52.91 63.67,52.68 63.84,52.51 64.52,52.51 64.69,52.34 64.69,52.11 64.52,51.94 63.84,51.94 63.67,51.77 63.67,51.54 63.84,51.37 64.52,51.37 64.69,51.2 64.69,50.97 64.52,50.8 63.84,50.8 63.67,50.63 63.67,50.4 63.84,50.23 64.52,50.23 64.69,50.06 64.69,49.83 64.52,49.66 63.84,49.66 63.67,49.49 63.67,49.26 63.84,49.09 64.52,49.09 64.69,48.92 64.69,48.69 64.52,48.52 63.84,48.52 63.67,48.35 63.67,48.08 63.84,47.92 64.5,47.92 64.67,47.75 64.67,47.51 64.5,47.35 63.84,47.35 63.67,47.18 63.67,40.77 70.69,33.75 70.69,26.56 71.78,25.46 v1(71.78,24.89)
GMAC0_RXDV_CRS: length 64.9
  TOP w0.156: R99.1 v1(71.91,69.06) R96.1 ; J2.59 v1(71.78,23.89)
  ART04 w0.142: v1(71.78,23.89) 71.27,24.4 71.27,25.37 70.26,26.39 70.26,33.55 63.25,40.56 63.25,53.57 63.41,53.74 64.1,53.74 64.27,53.91 64.27,54.14 64.1,54.31 63.41,54.31 63.25,54.48 63.25,54.71 63.41,54.88 64.1,54.88 64.27,55.05 64.27,55.28 64.1,55.45 63.41,55.45 63.25,55.62 63.25,55.85 63.41,56.02 63.59,56.02 63.76,56.19 63.76,69.79 64.05,70.07 70.89,70.07 v1(71.91,69.06)
GMAC0_TXCLK: length 72.9
  TOP w0.156: U18.20 67.9,74.7 66.84,73.64 v1(66.59,73.64) ; J2.51 v1(69.78,23.89)
  BOTTOM w0.156: v1(66.59,73.64) 66.33,73.64 65.39,72.7 65.39,64.04 63.46,62.11 62.17,62.11 59.79,59.74 59.79,49 60.1,48.69 67.26,48.69 67.57,48.38 67.57,47.35 67.76,47.16 68.02,47.16 68.2,47.35 68.2,48.56 68.38,48.74 68.64,48.74 68.83,48.56 68.83,47.35 69.01,47.16 69.27,47.16 69.45,47.35 69.45,48.56 69.63,48.74 70.08,48.74 70.28,48.54 70.28,24.39 v1(69.78,23.89)
GMAC0_TXD0: length 73.8
  TOP w0.156: J2.49 69.28,24.39 v1(68.78,24.89) ; U18.18 67.66,75.5 66.8,74.64 v1(66.59,74.64)
  BOTTOM w0.156: v1(66.59,74.64) 66.09,74.14 65.2,74.14 64.45,73.39 64.45,64.43 63.07,63.05 60.49,63.05 58.27,60.83 58.27,48.06 58.58,47.75 60.65,47.75 60.99,47.41 60.99,46.2 61.18,46.02 61.43,46.02 61.62,46.2 61.62,47.06 61.77,47.21 62.14,47.21 62.29,47.06 62.29,46.26 62.45,46.1 62.73,46.1 62.92,46.28 62.92,47.06 63.1,47.24 63.36,47.24 63.54,47.06 63.54,46.28 63.73,46.1 68.47,46.1 68.78,45.78 v1(68.78,24.89)
GMAC0_TXD1: length 73.2
  TOP w0.156: v1(65.59,74.64) 66.07,75.13 66.78,75.13 67.55,75.9 U18.17 ; J2.47 v1(68.78,23.89)
  BOTTOM w0.156: v1(65.59,74.64) 64.99,74.64 63.98,73.63 63.98,64.63 62.87,63.52 60.27,63.52 57.78,61.03 57.78,47.53 58.1,47.21 58.78,47.21 58.94,47.06 58.94,45.77 59.12,45.59 59.38,45.59 59.56,45.77 59.56,46.85 59.75,47.04 60.03,47.04 60.21,46.85 60.21,45.75 60.42,45.54 67.92,45.54 68.28,45.17 68.28,24.39 v1(68.78,23.89)
GMAC0_TXD2: length 72.4
  TOP w0.156: v1(66.59,75.64) 66.78,75.64 67.44,76.3 U18.16 ; J2.45 68.28,24.39 v1(67.78,24.89)
  BOTTOM w0.156: v1(67.78,24.89) 67.78,44.74 67.47,45.06 58.51,45.06 58.33,45.24 58.33,46.47 58.15,46.66 56.95,46.66 56.79,46.81 56.79,60.8 59.98,63.99 62.68,63.99 63.51,64.82 63.51,73.87 64.78,75.14 65.8,75.14 65.8,75.14 65.83,75.14 66.33,75.64 v1(66.59,75.64)
GMAC0_TXD3: length 73.4
  TOP w0.156: U18.15 67.33,76.7 66.76,76.13 66.07,76.13 v1(65.59,75.64) ; J2.43 v1(67.78,23.89)
  BOTTOM w0.156: v1(67.78,23.89) 67.28,24.39 67.28,44.23 66.97,44.55 56.62,44.55 56.31,44.86 56.31,61.11 59.66,64.46 62.48,64.46 63.04,65.02 63.04,74.2 64.48,75.64 v1(65.59,75.64)
GMAC0_TXEN: length 72.5
  TOP w0.156: J2.53 70.28,24.39 v1(69.78,24.89) ; v1(65.59,73.64) 66.08,74.14 66.88,74.14 67.84,75.1 U18.19
  BOTTOM w0.156: v1(65.59,73.64) 64.92,72.97 64.92,64.24 63.26,62.58 61.95,62.58 59.32,59.95 59.32,49.2 59.32,48.54 59.65,48.22 64.06,48.22 64.22,48.06 64.22,46.79 64.4,46.61 64.66,46.61 64.84,46.79 64.84,47.79 65,47.95 65.34,47.95 65.49,47.79 65.49,46.87 65.71,46.66 65.99,46.66 66.18,46.84 66.18,47.74 66.36,47.93 66.62,47.93 66.8,47.74 66.8,46.84 66.99,46.66 69.47,46.66 69.78,46.34 69.78,24.89 v1(69.78,24.89)
GMAC1_INT: length 86
  TOP w0.156: v1(35.28,60.94) 34.78,60.44 J3.12 ; R132.1 v1(96.77,72.06)
  ART03 w0.142: v1(96.77,72.06) 96.2,72.06 95.91,72.34 95.91,76.24 95.63,76.53 87.02,76.53 86.39,77.16 81.74,77.16 81.2,76.63 74.5,76.63 73.1,78.02 63.47,78.02 63.02,77.57 61.77,77.57 60.76,76.55 35.59,76.55 34.67,75.64 34.67,69.97 34.32,69.62 34.32,61.91 v1(35.28,60.94)
GMAC1_MCLKINOUT_M1: length 48.2
  TOP w0.156: J4.56 70.78,58.09 70.94,57.94 v1(71.78,57.94) ; R134.1 v1(96.77,76.12)
  BOTTOM w0.156: R135.1 96.76,76.14 v1(96.77,76.12) 97.3,76.12 97.61,75.81 97.61,71.75 97.13,71.27 91.62,71.27 90.73,72.16 82.98,72.16 82.3,71.47 82.3,65.83 79.25,62.78 79.25,57.76 78.94,57.45 72.9,57.45 72.41,57.94 v1(71.78,57.94)
GMAC1_MDC_M1: length 39.4
  TOP w0.156: U19.13 85.62,77.5 v1(84.77,76.64) ; J4.62 72.28,57.44 v1(71.78,56.94)
  ART04 w0.142: v1(71.78,56.94) 72.34,57.49 72.34,60.09 72.65,60.4 73.28,60.4 73.46,60.58 73.46,61.26 73.63,61.44 78.12,61.44 78.41,61.72 78.41,63.6 80.59,65.78 80.59,77.35 80.88,77.64 84.48,77.64 84.77,77.35 v1(84.77,76.64)
  BOTTOM w0.156: R128.2 83.83,76.64 v1(84.77,76.64)
GMAC1_MDIO_M1: length 37.3
  TOP w0.156: U19.14 86.22,77.1 v1(85.77,76.64) ; J4.60 v1(71.78,60.94)
  ART04 w0.142: v1(85.77,76.64) 85.77,78.53 85.48,78.81 80.4,78.81 80.11,78.53 80.11,65.91 76.76,62.56 72.55,62.56 72.26,62.27 72.26,61.41 v1(71.78,60.94)
  BOTTOM w0.156: v1(85.77,76.64) 85.05,77.36 R129.2
GMAC1_RSTN: length 74.3
  TOP w0.156: v1(84.77,72.64) 84.57,72.84 D35.2 ; J3.10 v1(34.28,60.94)
  ART03 w0.142: v1(84.77,72.64) 84.23,72.64 83.95,72.93 83.95,75.35 83.66,75.64 76.78,75.64 76.15,76.27 74.24,76.27 72.91,77.61 63.82,77.61 62.81,76.6 61.34,76.6 60.88,76.15 35.79,76.15 35.05,75.41 35.05,69.72 34.67,69.34 34.67,63.27 35.79,62.15 35.79,60.63 35.5,60.35 34.57,60.35 34.28,60.63 v1(34.28,60.94)
GMAC1_RXCLK_M1: length 56.3
  TOP w0.156: R117.2 v1(92.23,69.06) R123.1 ; J4.36 65.78,57.44 v1(65.28,56.94)
  BOTTOM w0.156: v1(65.28,56.94) 65.28,54.16 65.6,53.84 80.29,53.84 80.59,54.15 80.59,55.16 80.77,55.34 86.33,55.34 86.88,55.89 86.88,64.07 83.81,67.14 83.81,70.27 84.12,70.58 88.72,70.58 89.36,69.95 89.36,68.86 89.74,68.47 91.64,68.47 v1(92.23,69.06)
GMAC1_RXD0_M1: length 60.6
  TOP w0.156: R118.1 v1(89.94,69.06) R115.2 ; J4.34 v1(65.28,57.94)
  BOTTOM w0.156: v1(65.28,57.94) 65.94,57.28 65.94,54.69 66.25,54.38 75.99,54.38 76.17,54.56 76.17,55.64 76.35,55.83 76.61,55.83 76.8,55.64 76.8,54.56 76.98,54.38 77.24,54.38 77.42,54.56 77.42,55.64 77.61,55.83 77.86,55.83 78.05,55.64 78.05,54.56 78.23,54.38 78.49,54.38 78.67,54.56 78.67,55.64 78.86,55.83 79.12,55.83 79.3,55.64 79.3,54.56 79.48,54.38 79.74,54.38 79.93,54.56 79.93,55.64 80.11,55.83 86.1,55.83 86.41,56.14 86.41,63.83 83.31,66.93 83.31,70.78 83.62,71.09 89.6,71.09 89.94,70.75 v1(89.94,69.06)
GMAC1_RXD1_M1: length 56.1
  TOP w0.156: R119.1 v1(88.8,69.06) R116.2 ; J4.32 64.78,57.44 v1(64.28,56.94)
  BOTTOM w0.156: v1(64.28,56.94) 64.28,53.09 64.6,52.78 84.22,52.78 84.4,52.96 84.4,54.19 84.59,54.38 84.85,54.38 85.03,54.19 85.03,53.72 85.21,53.54 85.47,53.54 85.65,53.72 85.65,54.19 85.84,54.38 87.52,54.38 87.83,54.69 87.83,64.53 84.81,67.55 84.81,69.29 85.09,69.57 86.84,69.57 87.1,69.31 87.1,68.55 87.27,68.37 88.49,68.37 88.8,68.69 v1(88.8,69.06)
GMAC1_RXD2_M1: length 57.1
  TOP w0.156: R125.1 v1(87.66,69.06) R120.1 ; J4.30 v1(64.28,57.94)
  BOTTOM w0.156: v1(64.28,57.94) 64.78,57.44 64.78,57.15 64.79,57.15 64.79,53.6 65.1,53.29 81.06,53.29 81.25,53.47 81.25,54.59 81.43,54.77 81.69,54.77 81.87,54.59 81.87,53.47 82.06,53.29 82.32,53.29 82.5,53.47 82.5,54.59 82.68,54.77 82.94,54.77 83.12,54.59 83.12,53.47 83.31,53.29 83.57,53.29 83.75,53.47 83.75,54.69 83.93,54.87 87.04,54.87 87.35,55.19 87.35,64.3 84.31,67.35 84.31,69.76 84.62,70.07 87.34,70.07 87.66,69.76 v1(87.66,69.06)
GMAC1_RXD3_M1: length 56
  TOP w0.156: J4.28 63.78,57.44 v1(63.28,56.94) ; R122.1 v1(86.51,69.06) R126.1
  BOTTOM w0.156: v1(86.51,69.06) 86.08,68.63 86.08,66.99 88.3,64.77 88.3,52.43 88.08,52.21 87.72,52.21 87.52,52.41 87.52,53.72 87.34,53.91 87.08,53.91 86.9,53.72 86.9,52.38 86.71,52.19 86.43,52.19 86.25,52.38 86.25,52.87 86.06,53.06 85.8,53.06 85.62,52.87 85.62,52.38 85.44,52.19 63.6,52.19 63.28,52.51 v1(63.28,56.94)
GMAC1_RXDV_CRS_M1: length 58.9
  TOP w0.156: v1(66.78,56.94) 66.28,57.44 J4.38 ; R127.1 v1(91.08,69.06) R124.1
  BOTTOM w0.156: v1(66.78,56.94) 66.78,55.3 67.1,54.99 71.58,54.99 71.76,55.17 71.76,55.97 71.95,56.16 72.21,56.16 72.39,55.97 72.39,55.17 72.57,54.99 72.83,54.99 73.01,55.17 73.01,56.05 73.2,56.23 73.46,56.23 73.64,56.05 73.64,55.17 73.82,54.99 74.08,54.99 74.27,55.17 74.27,56.05 74.45,56.23 74.71,56.23 74.89,56.05 74.89,55.17 75.08,54.99 75.33,54.99 75.52,55.17 75.52,56.12 75.7,56.31 85.63,56.31 85.94,56.62 85.94,63.59 82.8,66.72 82.8,71.31 83.12,71.62 90.09,71.62 91.08,70.63 v1(91.08,69.06)
GMAC1_TXCLK_M1: length 39.3
  TOP w0.156: v1(85.77,73.64) 85.95,73.64 87,74.7 U19.20 ; J4.44 v1(67.78,57.94)
  BOTTOM w0.156: v1(67.78,57.94) 67.3,57.45 67.3,55.99 67.61,55.67 70.46,55.67 70.77,55.99 70.77,58.19 71.07,58.49 78.13,58.49 78.49,58.85 78.49,63.1 80.72,65.33 80.72,71.42 82.44,73.14 85.26,73.14 v1(85.77,73.64)
GMAC1_TXD0_M1: length 38.8
  TOP w0.156: U19.18 86.93,75.5 86.07,74.64 v1(85.77,74.64) ; J4.52 v1(69.78,57.94)
  BOTTOM w0.156: v1(85.77,74.64) 85.77,74.64 85.27,74.14 84.98,74.14 84.97,74.14 81.92,74.14 79.76,71.99 79.76,69.58 79.58,69.4 78.34,69.4 78.16,69.21 78.16,68.95 78.34,68.77 79.58,68.77 79.76,68.59 79.76,68.33 79.58,68.14 78.34,68.14 78.16,67.96 78.16,67.7 78.34,67.52 78.79,67.52 78.94,67.36 78.94,67.08 78.76,66.9 78.44,66.9 78.26,66.71 78.26,66.45 78.44,66.27 78.76,66.27 78.94,66.09 78.94,64.88 78.34,64.28 75.62,64.28 75.29,63.95 75.29,59.8 74.97,59.48 70.1,59.48 69.78,59.17 v1(69.78,57.94)
GMAC1_TXD1_M1: length 39.1
  TOP w0.156: J4.50 69.28,57.44 v1(69.78,56.94) ; U19.17 86.89,75.9 86.12,75.13 85.25,75.13 v1(84.77,74.64)
  BOTTOM w0.156: v1(84.77,74.64) 81.61,74.64 79.29,72.32 79.29,70.16 79.02,69.9 76.81,69.9 76.66,69.74 76.66,69.16 76.43,68.93 73.74,68.93 72.44,67.64 72.44,66.14 72.77,65.81 72.77,64.69 73.3,64.16 73.3,63.52 73.48,63.33 74.04,63.33 74.22,63.15 74.22,62.89 74.04,62.71 73.48,62.71 73.3,62.52 73.3,60.28 72.99,59.97 69.7,59.97 69.29,59.56 69.29,57.43 v1(69.78,56.94)
GMAC1_TXD2_M1: length 39.6
  TOP w0.156: J4.48 v1(68.78,57.94) ; v1(85.77,75.64) 86.16,75.64 86.82,76.3 U19.16
  BOTTOM w0.156: v1(85.77,75.64) 85.27,75.15 81.45,75.15 78.82,72.52 78.82,70.84 78.5,70.53 75.44,70.53 75.26,70.35 75.26,69.7 75.07,69.52 74.82,69.52 74.63,69.7 74.63,70.35 74.45,70.53 74.19,70.53 74.01,70.35 74.01,69.7 73.82,69.52 73.56,69.52 73.38,69.7 73.38,70.35 73.2,70.53 72.69,70.53 72.47,70.3 72.47,68.65 71.3,67.48 71.3,65.99 71.78,65.5 71.78,64.54 72.29,64.03 72.29,60.65 72.09,60.45 69.27,60.45 68.78,59.96 v1(68.78,57.94)
GMAC1_TXD3_M1: length 38.8
  TOP w0.156: J4.46 68.28,57.44 v1(68.78,56.94) ; v1(84.77,75.64) 85.25,76.13 86.09,76.13 86.66,76.7 U19.15
  BOTTOM w0.156: v1(68.78,56.94) 68.3,57.42 68.3,60.35 69.41,61.45 70.98,61.45 71.27,61.74 71.27,63.91 70.79,64.39 70.79,68.02 71.37,68.6 71.37,70.73 71.69,71.04 78.02,71.04 78.33,71.35 78.33,72.82 81.16,75.64 v1(84.77,75.64)
GMAC1_TXEN_M1: length 39.6
  TOP w0.156: U19.19 86.97,75.1 86.02,74.16 85.28,74.16 v1(84.77,73.64) ; v1(67.78,56.94) 67.28,57.44 J4.42
  BOTTOM w0.156: v1(67.78,56.94) 67.78,56.46 68.1,56.14 69.99,56.14 70.3,56.46 70.3,58.66 70.61,58.97 76.02,58.97 76.3,59.25 76.3,63.54 76.56,63.8 78.53,63.8 80.24,65.51 80.24,65.98 80.06,66.17 79.6,66.17 79.41,66.35 79.41,66.61 79.6,66.79 80.06,66.79 80.24,66.97 80.24,71.75 82.13,73.64 v1(84.77,73.64)
HDMI_5V: length 10
  ART03 w0.508: J21.18 56.76,81.65 57.07,81.96
  BOTTOM w0.305: J21.18 56.2,78.54 56.72,78.02 56.72,75.51 ; 56.72,75.51 57.12,75.1 R182.1 ; 56.72,75.51 56.31,75.1 R179.1
  vias: v1(58.12,96.59) v1(59.12,96.59)
HDMI_GND_CHASSIS: length 36.7
  ART03 w0.508: J21.G2 J21.G1 ; J21.G4 J21.G3
  BOTTOM w0.508: J21.G4 58.95,92.22 58.95,94.26 58.06,95.14 53.31,95.14 52.45,94.28 J21.G2 ; J21.G1 52.43,80.14 R177.1
HDMI_TX0N_PORT: length 68.8
  TOP w0.124: J21.9 54.79,87.26 53.71,87.26 50.42,83.96 50.42,77.99 50.5,77.9 U32.1 U32.10 50.5,76.17 50.42,76.08 50.42,75.33 50.56,75.18 51.43,75.18 51.77,74.84 51.77,74.37 51.45,74.06 50.44,74.06 50.29,73.91 50.29,73.7 50.44,73.56 51.4,73.56 51.77,73.19 51.77,72.72 51.4,72.36 50.42,72.36 50.29,72.23 50.29,72.06 50.49,71.86 51.45,71.86 51.77,71.55 51.77,71.07 51.43,70.74 50.56,70.74 50.42,70.59 50.42,70.02 v1(50.72,69.72) ; v1(44,54.73) 43.7,55.03 43.7,58.16 43.78,58.25 J3.48
  ART04 w0.113: v1(44,54.73) 43.69,54.43 43.69,53.82 43.31,53.44 41.76,53.44 41.38,53.82 41.38,58.4 41.16,58.62 40.24,58.62 39.9,58.96 39.9,69.16 40.61,69.87 47.18,69.87 47.6,70.29 47.6,72.28 48.13,72.82 49.91,72.82 50.41,72.32 50.41,70.02 v1(50.72,69.72)
HDMI_TX0P_PORT: length 67.2
  TOP w0.124: J3.46 43.28,58.25 43.37,58.16 43.37,55.03 v1(43.07,54.73) ; J21.7 54.79,87.59 53.58,87.59 50.09,84.1 50.09,77.99 50,77.9 U32.2 U32.9 50,76.17 50.09,76.08 50.09,75.19 50.43,74.85 51.29,74.85 51.44,74.71 51.44,74.51 51.31,74.38 50.3,74.38 49.96,74.05 49.96,73.57 50.3,73.23 51.26,73.23 51.44,73.06 51.44,72.86 51.31,72.74 50.3,72.74 49.96,72.4 49.96,71.92 50.35,71.54 51.31,71.54 51.44,71.41 51.44,71.21 51.29,71.07 50.43,71.07 50.09,70.73 50.09,70.02 v1(49.79,69.72)
  ART04 w0.113: v1(49.79,69.72) 50.1,70.02 50.1,72.19 49.78,72.5 48.26,72.5 47.92,72.15 47.92,70.16 47.31,69.56 40.75,69.56 40.22,69.03 40.22,59.09 40.37,58.94 41.29,58.94 41.69,58.53 41.69,53.95 41.89,53.75 43.18,53.75 43.38,53.95 43.38,54.43 v1(43.07,54.73)
HDMI_TX1N_PORT: length 67.6
  TOP w0.124: J3.44 42.78,57.94 v1(42.78,57.93) ; v1(59.98,73.76) 60.28,74.06 60.28,76.08 60.19,76.17 U31.9 U31.2 60.19,77.9 60.28,77.99 60.28,78.6 61.57,79.9 61.57,85.24 57.81,89 56.61,89 J21.6
  ART04 w0.113: v1(59.98,73.76) 60.29,73.45 60.29,72.97 60,72.69 59.76,72.69 arc(59.68,72.72) 59.65,72.8 59.65,72.86 arc(59.62,72.94) 59.53,72.97 59.31,72.97 arc(59.23,72.94) 59.2,72.86 59.2,72.8 arc(59.16,72.72) 59.08,72.69 58.86,72.69 arc(58.78,72.72) 58.75,72.8 58.75,72.86 arc(58.71,72.94) 58.63,72.97 58.41,72.97 arc(58.33,72.94) 58.3,72.86 58.3,72.8 arc(58.26,72.72) 58.18,72.69 57.96,72.69 arc(57.88,72.72) 57.84,72.8 57.84,72.86 arc(57.81,72.94) 57.73,72.97 57.51,72.97 arc(57.43,72.94) 57.39,72.86 57.39,72.8 arc(57.36,72.72) 57.28,72.69 57.06,72.69 arc(56.98,72.72) 56.94,72.8 56.94,72.86 arc(56.91,72.94) 56.83,72.97 56.61,72.97 arc(56.52,72.94) 56.49,72.86 56.49,72.8 arc(56.46,72.72) 56.38,72.69 56.16,72.69 arc(56.07,72.72) 56.04,72.8 56.04,72.86 arc(56.01,72.94) 55.92,72.97 55.7,72.97 arc(55.62,72.94) 55.59,72.86 55.59,72.8 arc(55.56,72.72) 55.47,72.69 55.25,72.69 arc(55.17,72.72) 55.14,72.8 55.14,72.86 arc(55.1,72.94) 55.02,72.97 54.8,72.97 arc(54.72,72.94) 54.69,72.86 54.69,72.8 arc(54.65,72.72) 54.57,72.69 54.21,72.69 53.76,72.24 53.76,72 arc(53.73,71.92) 53.65,71.89 arc(53.58,71.86) 53.54,71.78 53.54,71.55 arc(53.58,71.47) 53.65,71.44 arc(53.73,71.41) 53.76,71.33 53.76,71.1 arc(53.73,71.02) 53.65,70.99 arc(53.58,70.96) 53.54,70.88 53.54,70.64 arc(53.58,70.57) 53.65,70.54 arc(53.73,70.5) 53.76,70.43 53.76,67.5 53.62,67.36 53.13,67.36 52.99,67.49 52.99,68.13 52.7,68.42 52.21,68.42 51.91,68.13 51.91,67.49 51.78,67.36 51.59,67.36 51.46,67.49 51.46,68.08 51.12,68.42 50.67,68.42 50.38,68.13 50.38,67.49 50.24,67.36 50.06,67.36 49.93,67.49 49.93,68.08 49.58,68.42 49.14,68.42 48.84,68.13 48.84,67.49 48.71,67.36 48.52,67.36 48.39,67.49 48.39,68.08 48.05,68.42 47.61,68.42 47.31,68.13 47.31,67.49 47.18,67.36 46.99,67.36 46.86,67.49 46.86,68.08 46.51,68.42 46.07,68.42 45.77,68.13 45.77,67.49 45.64,67.36 42.83,67.36 42.38,66.9 42.38,64.61 arc(42.34,64.51) 42.25,64.47 arc(42.15,64.43) 42.11,64.34 42.11,64.15 arc(42.15,64.06) 42.25,64.02 arc(42.34,63.98) 42.38,63.89 42.38,63.7 arc(42.34,63.61) 42.25,63.57 arc(42.15,63.53) 42.11,63.44 42.11,63.25 arc(42.15,63.16) 42.25,63.12 arc(42.34,63.08) 42.38,62.98 42.38,60.48 42.68,60.18 43.34,60.18 43.55,59.98 43.55,59.74 arc(43.5,59.62) 43.38,59.56 arc(43.26,59.51) 43.21,59.39 43.21,59.29 arc(43.26,59.16) 43.38,59.11 arc(43.5,59.06) 43.55,58.94 43.55,57.81 43.36,57.63 43.09,57.63 v1(42.78,57.93)
HDMI_TX1P_PORT: length 66.1
  TOP w0.124: J3.42 42.28,57.5 v1(42.78,57) ; J21.4 56.61,89.32 57.95,89.32 61.9,85.37 61.9,79.76 60.6,78.47 60.6,77.99 60.69,77.9 U31.1 U31.10 60.69,76.17 60.6,76.08 60.6,74.06 v1(60.9,73.76)
  ART04 w0.113: v1(42.78,57) 43.09,57.31 43.5,57.31 43.87,57.68 43.87,60.11 43.47,60.5 42.81,60.5 42.7,60.61 42.7,66.77 42.97,67.04 45.77,67.04 46.09,67.36 46.09,68 46.2,68.11 46.38,68.11 46.54,67.95 46.54,67.36 46.86,67.04 47.31,67.04 47.62,67.36 47.62,68 47.74,68.11 47.92,68.11 48.08,67.95 48.08,67.36 48.39,67.04 48.84,67.04 49.16,67.36 49.16,68 49.27,68.11 49.45,68.11 49.61,67.95 49.61,67.36 49.93,67.04 50.38,67.04 50.69,67.36 50.69,68 50.81,68.11 50.99,68.11 51.14,67.95 51.14,67.36 51.46,67.04 51.91,67.04 52.23,67.36 52.23,68 52.34,68.11 52.56,68.11 52.68,68 52.68,67.36 52.99,67.04 53.75,67.04 54.08,67.37 54.08,72.11 54.34,72.37 60.13,72.37 60.6,72.84 60.6,73.46 v1(60.9,73.76)
HDMI_TX2N_PORT: length 66.4
  TOP w0.124: v1(43.03,72.59) 42.73,72.89 42.73,74.96 43.08,75.31 48.57,75.31 48.92,75.66 48.92,76.08 49,76.17 U32.7 U32.4 49,77.9 48.92,77.99 48.92,89.05 51.77,91.89 53,91.89 54.17,90.72 54.79,90.72 J21.3 ; v1(40.28,53.9) 40.58,54.2 41.36,54.2 41.7,54.54 41.7,58.16 41.78,58.25 J3.40
  ART04 w0.113: v1(40.28,53.9) 39.98,54.2 38.49,54.2 37.91,54.78 37.91,60.06 36.92,61.05 36.92,73.16 37.93,74.18 42.25,74.18 42.73,73.7 42.73,72.89 v1(43.03,72.59)
HDMI_TX2P_PORT: length 64.8
  TOP w0.124: v1(40.28,54.83) 40.58,54.53 41.22,54.53 41.37,54.67 41.37,58.16 41.28,58.25 J3.38 ; v1(42.11,72.59) 42.41,72.89 42.41,75.1 42.95,75.64 48.43,75.64 48.59,75.8 48.59,76.08 48.5,76.17 U32.6 U32.5 48.5,77.9 48.59,77.99 48.59,89.18 51.63,92.22 53.14,92.22 54.31,91.05 54.79,91.05 J21.1
  ART04 w0.113: v1(40.28,54.83) 39.98,54.52 38.62,54.52 38.23,54.91 38.23,60.19 37.24,61.18 37.24,73.03 38.06,73.86 42.12,73.86 42.41,73.57 42.41,72.89 v1(42.11,72.59)
HDMI_TX_CEC_PORT: length 13.6
  BOTTOM w0.156: J21.13 54.03,84.53 53.59,84.1 53.59,76.53 53.21,76.15 D18.2 51.46,75.44 Q7.3
